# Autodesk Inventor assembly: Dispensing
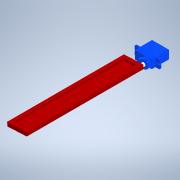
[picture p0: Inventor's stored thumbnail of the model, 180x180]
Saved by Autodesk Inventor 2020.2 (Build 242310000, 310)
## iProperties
Created: 2020-04
Part Number: Dispensing
Document SubType Name: Assembly
Designer: kshit
Author: kshit
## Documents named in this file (3)
- D:\College\SEM-2\EnggExplo\KSHITIJ\Dispensing.iam
- C:\Users\kshit\Downloads\servo-motor-sg90-3.snapshot.3\Servo Motor SG90.ipt
- C:\Users\kshit\OneDrive\Documents\My Games\Part1.ipt
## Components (2 placed, 2 different names)
1. Servo Motor SG90:1 — Insert:1
2. Part1:1 — Insert:1
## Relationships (1: Insert 1)
- Insert:1: Servo Motor SG90:1 ↔ Part1:1
